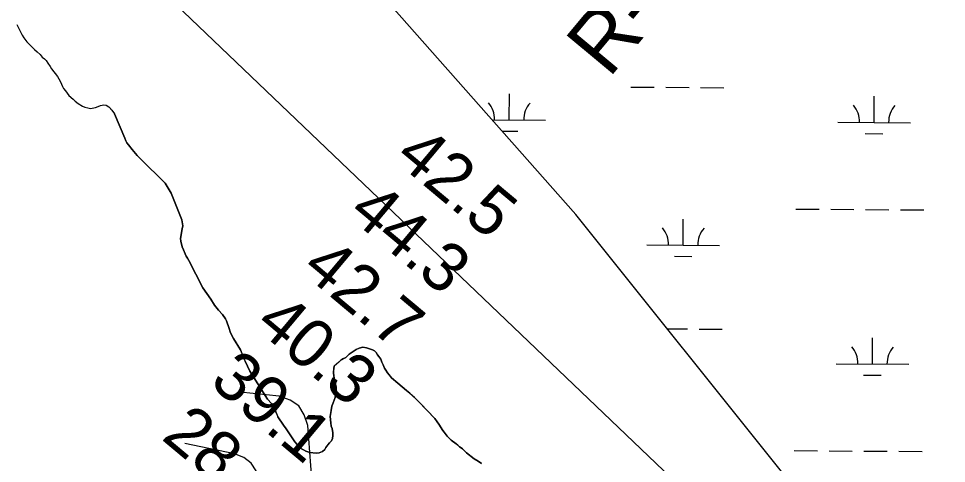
# Model space of a CAD drawing. Extents: x 3172231 to 3210228, y 940198 to 965780.
# Drawn here: x 3194853 to 3196129, y 948908 to 949521 of the extents above; entities that cross this region are included whole.
import ezdxf

# ---------------------------------------------------------------- set-up
doc = ezdxf.new("R2010")
doc.units = 0
for name, color, linetype in [('V-RIVR-RANG', 7, 'Continuous'), ('V-RIVR-RANG-IDEN', 7, 'Continuous'), ('V-SITE-VEGE', 7, 'Continuous'), ('V-TOPO-BNDY', 7, 'Continuous'), ('V-TOPO-MAJR', 7, 'Continuous'), ('V-TOPO-MINR', 7, 'Continuous'), ('V-TOPO-SHOR', 7, 'Continuous'), ('V-WETL-SWMP', 7, 'Continuous')]:
    doc.layers.add(name, color=color, linetype=linetype)

msp = doc.modelspace()

# ---------------------------------------------------------------- linework, layer by layer
at = {"layer": 'V-SITE-VEGE'}
for p, q in [((3194850.719, 949512.263), (3194858.096, 949497.515)), ((3194858.096, 949497.515), (3194860.193, 949494.089)), ((3194860.193, 949494.089), (3194864.383, 949488.271)), ((3194864.383, 949488.271), (3194866.818, 949485.537)), ((3194866.818, 949485.537), (3194874.817, 949477.687)), ((3194874.817, 949477.687), (3194878.637, 949474.621)), ((3194878.637, 949474.621), (3194882.463, 949470.867)), ((3194882.463, 949470.867), (3194885.596, 949467.451)), ((3194885.596, 949467.451), (3194888.373, 949465.065)), ((3194888.373, 949465.065), (3194890.808, 949462.675)), ((3194890.808, 949462.675), (3194893.254, 949459.253)), ((3194893.254, 949459.253), (3194896.399, 949454.456)), ((3194896.399, 949454.456), (3194898.15, 949451.372)), ((3194898.15, 949451.372), (3194906.521, 949440.767)), ((3194906.521, 949440.767), (3194910.371, 949434.257)), ((3194910.371, 949434.257), (3194912.132, 949430.138)), ((3194912.132, 949430.138), (3194913.195, 949427.048)), ((3194913.195, 949427.048), (3194914.944, 949424.308)), ((3194914.944, 949424.308), (3194917.387, 949420.883)), ((3194917.387, 949420.883), (3194919.828, 949417.805)), ((3194919.828, 949417.805), (3194921.924, 949414.725)), ((3194921.924, 949414.725), (3194928.174, 949409.613)), ((3194928.174, 949409.613), (3194930.957, 949406.883)), ((3194930.957, 949406.883), (3194935.123, 949403.477)), ((3194935.123, 949403.477), (3194941.015, 949399.742)), ((3194941.015, 949399.742), (3194944.13, 949398.392)), ((3194944.13, 949398.392), (3194948.273, 949397.741)), ((3194948.273, 949397.741), (3194952.07, 949396.744)), ((3194952.07, 949396.744), (3194958.949, 949398.185)), ((3194958.949, 949398.185), (3194962.382, 949399.596)), ((3194962.382, 949399.596), (3194965.472, 949400.657)), ((3194965.472, 949400.657), (3194970.287, 949401.737)), ((3194970.287, 949401.737), (3194973.394, 949401.077)), ((3194973.394, 949401.077), (3194976.859, 949399.041)), ((3194976.859, 949399.041), (3194979.292, 949396.653)), ((3194979.292, 949396.653), (3194979.296, 949396.307)), ((3194979.296, 949396.307), (3194981.383, 949394.259)), ((3194981.383, 949394.259), (3194984.877, 949389.125)), ((3194984.877, 949389.125), (3194998.977, 949355.898)), ((3194998.977, 949355.898), (3195000.45, 949351.948)), ((3195000.45, 949351.948), (3195001.951, 949349.175)), ((3195001.951, 949349.175), (3195004.235, 949346.377)), ((3195004.235, 949346.377), (3195009.177, 949339.996)), ((3195009.177, 949339.996), (3195011.468, 949337.591)), ((3195011.468, 949337.591), (3195016.037, 949332.002)), ((3195016.037, 949332.002), (3195020.623, 949327.193)), ((3195020.623, 949327.193), (3195054.693, 949293.893)), ((3195054.693, 949293.893), (3195062.998, 949280.044)), ((3195062.998, 949280.044), (3195077.389, 949243.234)), ((3195077.389, 949243.234), (3195078.761, 949234.978)), ((3195077.887, 949231.085), (3195075.608, 949217.431)), ((3195078.761, 949234.978), (3195077.887, 949231.085)), ((3195075.608, 949217.431), (3195075.917, 949213.898)), ((3195075.917, 949213.898), (3195078.081, 949206.015)), ((3195078.081, 949206.015), (3195079.945, 949202.057)), ((3195079.945, 949202.057), (3195082.167, 949196.523)), ((3195082.167, 949196.523), (3195083.658, 949193.353)), ((3195083.658, 949193.353), (3195085.159, 949190.578)), ((3195085.159, 949190.578), (3195087.041, 949187.399)), ((3195087.041, 949187.399), (3195106.52, 949149.74)), ((3195106.52, 949149.74), (3195117.501, 949133.817)), ((3195117.501, 949133.817), (3195122.406, 949125.871)), ((3195122.406, 949125.871), (3195127.721, 949118.697)), ((3195127.721, 949118.697), (3195133.453, 949112.688)), ((3195133.453, 949112.688), (3195137.629, 949107.107)), ((3195137.629, 949107.107), (3195139.13, 949104.332)), ((3195139.13, 949104.332), (3195142.796, 949093.672)), ((3195142.796, 949093.672), (3195143.859, 949088.948)), ((3195143.859, 949088.948), (3195145.752, 949084.841)), ((3195145.752, 949084.841), (3195148.344, 949079.836)), ((3195148.344, 949079.836), (3195158.162, 949064.333)), ((3195158.162, 949064.333), (3195162.973, 949052.473)), ((3195307.615, 949058.471), (3195317.165, 949064.904)), ((3195317.165, 949064.904), (3195321.507, 949066.368)), ((3195321.507, 949066.368), (3195326.631, 949067.814)), ((3195326.631, 949067.814), (3195331.308, 949066.919)), ((3195331.308, 949066.919), (3195334.421, 949066.065)), ((3195334.421, 949066.065), (3195339.865, 949064.372)), ((3195339.865, 949064.372), (3195342.566, 949062.741)), ((3195342.566, 949062.741), (3195344.86, 949060.337)), ((3195162.973, 949052.473), (3195164.448, 949048.52)), ((3195287.25, 949041.721), (3195296.062, 949050.128)), ((3195296.062, 949050.128), (3195303.2, 949053.876)), ((3195303.2, 949053.876), (3195307.615, 949058.471)), ((3195344.86, 949060.337), (3195346.752, 949057.552)), ((3195346.752, 949057.552), (3195348.655, 949055.158)), ((3195348.655, 949055.158), (3195351.303, 949051.178)), ((3195351.303, 949051.178), (3195352.776, 949047.228)), ((3195164.448, 949048.52), (3195171.171, 949034.657)), ((3195286.246, 949032.345), (3195286.394, 949038.608)), ((3195286.394, 949038.608), (3195287.25, 949041.721)), ((3195352.776, 949047.228), (3195354.258, 949043.668)), ((3195354.258, 949043.668), (3195356.497, 949038.917)), ((3195356.497, 949038.917), (3195357.998, 949036.142)), ((3195357.998, 949036.142), (3195360.263, 949032.562)), ((3195171.171, 949034.657), (3195195.334, 948996.497)), ((3195286.545, 949028.421), (3195286.246, 949032.345)), ((3195287.918, 949020.165), (3195286.545, 949028.421)), ((3195360.263, 949032.562), (3195365.977, 949025.773)), ((3195365.977, 949025.773), (3195374.423, 949018.525)), ((3195289.019, 949017.007), (3195287.918, 949020.165)), ((3195289.699, 949012.684), (3195289.019, 949017.007)), ((3195289.972, 949007.587), (3195289.699, 949012.684)), ((3195374.423, 949018.525), (3195386.316, 949008.064)), ((3195285.673, 948991.242), (3195288.585, 948998.612)), ((3195288.585, 948998.612), (3195289.972, 949007.587)), ((3195386.316, 949008.064), (3195390.93, 949004.431)), ((3195390.93, 949004.431), (3195403.197, 948993.179)), ((3195195.334, 948996.497), (3195201.062, 948990.097)), ((3195201.062, 948990.097), (3195202.944, 948986.918)), ((3195202.944, 948986.918), (3195205.944, 948981.364)), ((3195282.685, 948980.737), (3195283.602, 948986.591)), ((3195283.602, 948986.591), (3195285.673, 948991.242)), ((3195403.197, 948993.179), (3195425.355, 948969.553)), ((3195205.944, 948981.364), (3195209.639, 948971.884)), ((3195281.708, 948972.537), (3195282.685, 948980.737)), ((3195282.279, 948963.518), (3195281.708, 948972.537)), ((3195209.639, 948971.884), (3195217.198, 948960.348)), ((3195217.198, 948960.348), (3195221.003, 948955.557)), ((3195282.961, 948959.192), (3195282.279, 948963.518)), ((3195425.355, 948969.553), (3195428.777, 948965.164)), ((3195428.777, 948965.164), (3195431.05, 948961.98)), ((3195431.05, 948961.98), (3195436.328, 948953.239)), ((3195221.003, 948955.557), (3195233.113, 948937.652)), ((3195284.061, 948956.034), (3195282.961, 948959.192)), ((3195285.097, 948950.136), (3195284.061, 948956.034)), ((3195285.396, 948946.212), (3195285.097, 948950.136)), ((3195436.328, 948953.239), (3195442.404, 948945.264)), ((3195233.113, 948937.652), (3195236.152, 948933.664)), ((3195275.607, 948929.605), (3195280.461, 948936.148)), ((3195280.461, 948936.148), (3195283.264, 948938.823)), ((3195283.264, 948938.823), (3195284.913, 948942.309)), ((3195284.913, 948942.309), (3195285.396, 948946.212)), ((3195442.404, 948945.264), (3195448.147, 948939.648)), ((3195448.147, 948939.648), (3195454.69, 948934.795)), ((3195454.69, 948934.795), (3195459.294, 948930.77)), ((3195236.152, 948933.664), (3195239.982, 948930.049)), ((3195239.982, 948930.049), (3195242.286, 948928.038)), ((3195242.286, 948928.038), (3195244.987, 948926.408)), ((3195244.987, 948926.408), (3195248.084, 948924.77)), ((3195248.084, 948924.77), (3195253.513, 948922.683)), ((3195253.513, 948922.683), (3195262.508, 948922.081)), ((3195262.508, 948922.081), (3195266.432, 948922.38)), ((3195266.432, 948922.38), (3195271.173, 948924.227)), ((3195271.173, 948924.227), (3195273.979, 948926.902)), ((3195273.979, 948926.902), (3195275.607, 948929.605)), ((3195459.294, 948930.77), (3195463.536, 948927.93)), ((3195463.536, 948927.93), (3195469.278, 948922.312)), ((3195469.278, 948922.312), (3195479.662, 948914.237)), ((3195479.662, 948914.237), (3195485.066, 948910.976)), ((3195485.066, 948910.976), (3195489.691, 948907.734))]:
    msp.add_line(p, q, dxfattribs=at)
at = {"layer": 'V-TOPO-BNDY'}
msp.add_line((3194332.024, 950245.511), (3197716.878, 947007.215), dxfattribs=at)
at = {"layer": 'V-TOPO-MAJR'}
msp.add_lwpolyline([(3195258.938, 948850.046), (3195250.642, 948959.823), (3195245.961, 948974.907), (3195238.352, 948987.151), (3195226.35, 948995.138), (3195211.419, 949000.286), (3195157.516, 949006.052)], dxfattribs=at)
at = {"layer": 'V-TOPO-MINR'}
msp.add_lwpolyline([(3195198.48, 948779.828), (3195184.19, 948884.587), (3195179.701, 948897.56), (3195172.88, 948908.347), (3195162.558, 948915.854), (3195149.904, 948921.175), (3195081.635, 948935.05)], dxfattribs=at)
at = {"layer": 'V-TOPO-SHOR'}
for points in [[(3194850.719, 949512.263), (3194858.094, 949497.515), (3194860.193, 949494.089), (3194864.383, 949488.271), (3194866.818, 949485.537), (3194874.817, 949477.687), (3194878.637, 949474.621), (3194882.463, 949470.867), (3194885.596, 949467.451), (3194888.373, 949465.065), (3194890.808, 949462.675), (3194893.254, 949459.253), (3194896.399, 949454.456), (3194898.15, 949451.372), (3194906.521, 949440.767), (3194910.371, 949434.257), (3194912.132, 949430.138), (3194913.195, 949427.048), (3194914.944, 949424.308), (3194917.387, 949420.883), (3194919.828, 949417.805), (3194921.924, 949414.725), (3194928.174, 949409.613), (3194930.957, 949406.883), (3194935.123, 949403.475), (3194941.015, 949399.742), (3194944.13, 949398.392), (3194948.271, 949397.741), (3194952.07, 949396.744), (3194958.949, 949398.185), (3194962.382, 949399.596), (3194965.472, 949400.657), (3194970.287, 949401.737), (3194973.394, 949401.077), (3194976.859, 949399.041), (3194979.292, 949396.653), (3194979.296, 949396.307), (3194981.383, 949394.259), (3194984.877, 949389.125)], [(3195242.286, 948928.038), (3195239.982, 948930.049), (3195236.152, 948933.664), (3195233.113, 948937.652), (3195229.328, 948943.222), (3195226.68, 948947.201), (3195221.003, 948955.557), (3195217.198, 948960.348), (3195209.639, 948971.882), (3195208.902, 948973.856), (3195207.419, 948977.416), (3195205.944, 948981.366), (3195204.443, 948984.143), (3195203.317, 948986.128), (3195202.944, 948986.918), (3195201.06, 948990.097), (3195195.336, 948996.497), (3195171.171, 949034.657), (3195164.448, 949048.52), (3195162.973, 949052.473), (3195160.755, 949058.006), (3195158.162, 949064.333), (3195148.344, 949079.836), (3195145.752, 949084.843), (3195143.859, 949088.948), (3195142.796, 949093.672), (3195139.13, 949104.332), (3195137.629, 949107.107), (3195133.453, 949112.688), (3195127.721, 949118.697), (3195122.406, 949125.871), (3195117.503, 949133.817), (3195106.52, 949149.74), (3195087.041, 949187.399), (3195085.159, 949190.578), (3195083.658, 949193.353), (3195082.165, 949196.521), (3195079.945, 949202.057), (3195078.081, 949206.015), (3195075.917, 949213.898), (3195075.608, 949217.431), (3195077.887, 949231.083), (3195078.761, 949234.978), (3195077.389, 949243.234), (3195062.998, 949280.044), (3195054.693, 949293.893), (3195020.623, 949327.196), (3195016.037, 949332.002), (3195011.468, 949337.591), (3195009.177, 949339.996), (3195004.235, 949346.377), (3195001.951, 949349.173), (3195000.45, 949351.948), (3194998.977, 949355.898), (3194984.877, 949389.125)], [(3195489.691, 948907.734), (3195485.066, 948910.976), (3195479.662, 948914.237), (3195469.278, 948922.312), (3195463.536, 948927.93), (3195461.606, 948929.148), (3195459.294, 948930.77), (3195456.992, 948932.781), (3195454.69, 948934.795), (3195448.147, 948939.646), (3195442.404, 948945.264), (3195438.228, 948950.845), (3195436.328, 948953.239), (3195431.05, 948961.98), (3195428.777, 948965.164), (3195425.355, 948969.553), (3195405.872, 948990.373), (3195403.197, 948993.179), (3195397.447, 948998.403), (3195391.313, 949004.029), (3195390.93, 949004.431), (3195386.316, 949008.064), (3195374.423, 949018.525), (3195365.977, 949025.773), (3195362.93, 949029.367), (3195360.263, 949032.562), (3195357.998, 949036.142), (3195356.497, 949038.917), (3195354.258, 949043.668), (3195352.776, 949047.228), (3195351.303, 949051.178), (3195348.655, 949055.158), (3195346.752, 949057.552), (3195344.86, 949060.337), (3195342.566, 949062.741), (3195339.865, 949064.372), (3195334.421, 949066.065), (3195331.308, 949066.921), (3195326.631, 949067.814), (3195321.507, 949066.368), (3195317.165, 949064.904), (3195307.615, 949058.471), (3195303.2, 949053.876), (3195298.84, 949051.629), (3195296.062, 949050.128), (3195293.259, 949047.451), (3195290.054, 949044.395), (3195287.25, 949041.721), (3195286.394, 949038.608), (3195286.32, 949035.476), (3195286.246, 949032.345), (3195286.545, 949028.423), (3195287.918, 949020.165), (3195289.019, 949017.007), (3195289.699, 949012.684), (3195289.972, 949007.587), (3195288.585, 948998.612), (3195285.673, 948991.242), (3195283.604, 948986.591), (3195282.685, 948980.737), (3195281.708, 948972.537), (3195282.279, 948963.518), (3195282.961, 948959.192), (3195284.061, 948956.034), (3195285.097, 948950.136), (3195285.396, 948946.212), (3195284.913, 948942.309), (3195283.264, 948938.823), (3195280.461, 948936.148), (3195278.439, 948933.453), (3195275.607, 948929.605), (3195273.979, 948926.902), (3195271.173, 948924.227), (3195266.432, 948922.38), (3195262.508, 948922.081), (3195253.515, 948922.683), (3195248.084, 948924.77), (3195244.987, 948926.408), (3195242.286, 948928.038)]]:
    msp.add_lwpolyline(points, dxfattribs=at)
at = {"layer": 'V-WETL-SWMP'}
for p, q in [((3195619.376, 949250.55), (3195064.919, 949879.193)), ((3195695.152, 949426.154), (3195727.151, 949425.936)), ((3195743.151, 949425.827), (3195775.15, 949425.61)), ((3195791.15, 949425.501), (3195823.149, 949425.283)), ((3195527.776, 949380.862), (3195528.021, 949416.862)), ((3196029.672, 949377.446), (3196029.917, 949413.445)), ((3195504.301, 949381.022), (3195577.775, 949380.522)), ((3195979.674, 949377.786), (3196079.671, 949377.106)), ((3195517.993, 949365.498), (3195539.671, 949365.35)), ((3196017.568, 949362.097), (3196041.567, 949361.934)), ((3195922.014, 949258.105), (3195954.013, 949257.887)), ((3195970.012, 949257.778), (3196002.012, 949257.56)), ((3196018.011, 949257.451), (3196050.011, 949257.234)), ((3196066.01, 949257.125), (3196098.009, 949256.907)), ((3195915.087, 948880.76), (3195619.376, 949250.55)), ((3195767.08, 949208.416), (3195767.325, 949244.416)), ((3195717.081, 949208.757), (3195817.079, 949208.076)), ((3195754.975, 949193.067), (3195778.974, 949192.904)), ((3195745.26, 949093.13), (3195772.886, 949092.942)), ((3195788.885, 949092.833), (3195820.885, 949092.616)), ((3196027.408, 949044.779), (3196027.653, 949080.778)), ((3195977.409, 949045.119), (3196077.407, 949044.438)), ((3196015.303, 949029.43), (3196039.303, 949029.266)), ((3195919.749, 948925.438), (3195951.748, 948925.22)), ((3195967.748, 948925.111), (3195999.747, 948924.893)), ((3196015.747, 948924.784), (3196047.746, 948924.566)), ((3196063.746, 948924.457), (3196095.745, 948924.24))]:
    msp.add_line(p, q, dxfattribs=at)
for centre, start, end in [((3195472.538, 949381.713), 358.838165, 40.381824), ((3195583.021, 949380.961), 138.838162, 180.381821), ((3195974.434, 949378.297), 358.838165, 40.381824), ((3196084.917, 949377.545), 138.838162, 180.381821), ((3195711.841, 949209.267), 358.838165, 40.381824), ((3195822.325, 949208.515), 138.838162, 180.381821), ((3195972.169, 949045.629), 358.838165, 40.381824), ((3196082.653, 949044.877), 138.838162, 180.381821)]:
    msp.add_arc(centre, 35.246, start, end, dxfattribs=at)

# ---------------------------------------------------------------- texts
at = {"layer": 'V-RIVR-RANG'}
for s, p in [('42.5', (3195368.132, 949325.971)), ('44.3', (3195304.075, 949249.181)), ('42.7', (3195240.018, 949172.391)), ('40.3', (3195175.962, 949095.601)), ('39.1', (3195113.724, 949017.285)), ('28.4', (3195047.848, 948942.02))]:
    msp.add_text(s, height=67, rotation=320.028326, dxfattribs=at).set_placement(p)
at = {"layer": 'V-RIVR-RANG-IDEN'}
msp.add_text('R-314.05', height=82.9998, rotation=50.165881, dxfattribs=at).set_placement((3195664.87, 949437.019))

doc.saveas('drawing.dxf')
